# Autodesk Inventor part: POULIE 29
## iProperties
Created: 2004-11
Part Number: POULIE 29
Document SubType Name: Modeling
Designer: Bruno
Manufacturer: Standard
Standards Organization: Custom
Author: Bruno
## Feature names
1. Base1
